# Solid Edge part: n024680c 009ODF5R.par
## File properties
Title: Bearing NA 4907
Comments: Sharon Richards Bearing Int. 011345 8160  R126-00  OD 55 ID 35 LENGTH 20
Template: Normal.par
Last saved by: Dan
Revision: 27
Application: Solid Edge
Document Number: P52-006
Project Name: Piston Pump P52
Mscpartversion: 2
ProtocolId (internal): P00040723104706972
Protocol (internal): P00040723104706972<@PID>[CalcData]<@EL>CalcResult=False<@EL>[LOGS]<@EL>7=2004/07/23 12:49:45 PM: ~The Strength Check is OK.~-2147483640~~~txtcheck<@EL>6=~--------------------------------------------------------------------------------------------~-2147483640~~~<@EL>5=2004/07/23 12:47:48 PM: ~The Strength Check is False.~255~~~txtcheck<@EL>4=2004/07/23 12:47:48 PM: ~Calculated bearing life is smaller then required.~255~~~var21<@EL>3=~--------------------------------------------------------------------------------------------~-2147483640~~~<@EL>2=2004/07/23 12:47:16 PM: ~The Strength Check is OK.~-2147483640~~~txtcheck<@EL>1=~--------------------------------------------------------------------------------------------~-2147483640~~~<@EL>8=~--------------------------------------------------------------------------------------------~-2147483640~~~<@EL>9=2004/07/23 12:50:31 PM: ~Bearing load is less than recommended minimum load.~255~~~var20<@EL>10=2004/07/23 12:50:31 PM: ~The Strength Check is False.~255~~~txtcheck<@EL>11=~--------------------------------------------------------------------------------------------~-2147483640~~~<@EL>12=2004/07/23 12:50:43 PM: ~Bearing load is less than recommended minimum load.~255~~~var20<@EL>13=2004/07/23 12:50:43 PM: ~The Strength Check is False.~255~~~txtcheck<@EL>[Data]<@EL>Scn1=1{ND<@EL>ot=1450{rpm<@EL>Lh_in=10000{h<@EL>V=1{ND<@EL>SIunits=1{ND<@EL>fd=1{ND<@EL>ft=100{°C<@EL>a1=90{%<@EL>d=35{mm<@EL>DD=55{mm<@EL>B=20{mm<@EL>r=0.6{mm<@EL>damin=39{mm<@EL>Damax=51{mm<@EL>ramax=0.6{mm<@EL>mass=0.17{kg<@EL>P=200{N<@EL>P0=200{N<@EL>s0=270{ND<@EL>Pz=1.33{W<@EL>Fmin=638{N<@EL>Lh=252938907.1{h<@EL>kn=6.55{ND<@EL>typ=NA 4907{<@EL>Ni=1{ND<@EL>Fr0=200{N<@EL>Fa0=0{N<@EL>n0=1450{rpm<@EL>t0=100{%<@EL>Ready=8{ND<@EL>Fw=42{mm<@EL>[Synchronize]<@EL>ChangedVars=<@EL>[Calc]<@EL>CalcName=BEARINGS<@EL>Optim=1<@EL>WizardMode=2<@EL>ScnVisible=1<@EL>Bmax=<@EL>Bmin=<@EL>Dmax=<@EL>Dmin=<@EL>DDmax=<@EL>DDmin=<@EL>[BaseView]<@EL>NewProt=P00040723104706972<@EL>OnT
BOM1: Bearing
BOM2: SKF NA 4907
Density: 0.0000078 kg/mm^3
Accuracy: 0.01
Material: steel
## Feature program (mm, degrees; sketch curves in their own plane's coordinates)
sketch for "unnamed RevolvedProtrusion 1" plane through (0, 0, 0) normal (0, 0, 1) x-axis (1, 0, 0)
  line (10, 22.955) -> (10, 27.5)
  line (10, 27.5) -> (-10, 27.5)
  line (-10, 27.5) -> (-10, 22.955)
  line (-10, 22.955) -> (-7, 22.955)
  line (-7, 23.61) -> (-7, 22.955)
  line (-7, 23.61) -> (7, 23.61)
  line (7, 23.61) -> (7, 22.955)
  line (10, 22.955) -> (7, 22.955)
revolve "unnamed RevolvedProtrusion 1" add
sketch for "unnamed RevolvedProtrusion 2" plane through (0, 0, 0) normal (0, 0, 1) x-axis (1, 0, 0)
  line (10, 20.1962) -> (7, 21)
  line (-7, 21) -> (7, 21)
  line (-7, 21) -> (-10, 20.1962)
  line (-10, 20.1962) -> (-10, 17.5)
  line (-10, 17.5) -> (10, 17.5)
  line (10, 17.5) -> (10, 20.1962)
revolve "unnamed RevolvedProtrusion 2" add
fillet "unnamed Round 1"
sketch for "unnamed RevolvedProtrusion 3" plane through (0, 0, 0) normal (0, 0, 1) x-axis (1, 0, 0)
  line (-7, 22.305) -> (7, 22.305)
  line (7, 23.605) -> (7, 22.305)
  line (-7, 23.605) -> (7, 23.605)
  line (-7, 22.305) -> (-7, 23.605)
revolve "unnamed RevolvedProtrusion 3" add about sketch line (-3.0987, 22.305) -> (3.798, 22.305)
pattern "unnamed Pattern 1" of "unnamed RevolvedProtrusion 3"
revolve "unnamed RevolvedProtrusion 4" add
revolve "unnamed RevolvedProtrusion 5" add
revolve "unnamed RevolvedProtrusion 6" add
revolve "unnamed RevolvedProtrusion 7" add
revolve "unnamed RevolvedProtrusion 8" add
revolve "unnamed RevolvedProtrusion 9" add
revolve "unnamed RevolvedProtrusion 10" add
revolve "unnamed RevolvedProtrusion 11" add
revolve "unnamed RevolvedProtrusion 12" add
revolve "unnamed RevolvedProtrusion 13" add
revolve "unnamed RevolvedProtrusion 14" add
revolve "unnamed RevolvedProtrusion 15" add
revolve "unnamed RevolvedProtrusion 16" add
revolve "unnamed RevolvedProtrusion 17" add
revolve "unnamed RevolvedProtrusion 18" add
revolve "unnamed RevolvedProtrusion 19" add
revolve "unnamed RevolvedProtrusion 20" add
revolve "unnamed RevolvedProtrusion 21" add
revolve "unnamed RevolvedProtrusion 22" add
revolve "unnamed RevolvedProtrusion 23" add
revolve "unnamed RevolvedProtrusion 24" add
revolve "unnamed RevolvedProtrusion 25" add
revolve "unnamed RevolvedProtrusion 26" add
revolve "unnamed RevolvedProtrusion 27" add
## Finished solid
Body 1: solid body, 93 faces, 216 edges, 100 vertices, 2 separate solids.
  Faces by surface: plane 56, cylinder 31, torus 4, cone 2
  Edges by curve: circle 216
Bounding box of the edges (mm; curved faces can reach further): 20.000 x 55.000 x 55.000, from (-10, -27.5, -27.5) to (10, 27.5, 27.5).
Cylindrical faces by radius (mm): R1.3 x25, R17.5 x1, R21 x1, R22.955 x2, R23.61 x1, R27.5 x1
Conical faces (half-angle, radius in mm at the cone's reference point): 15 deg R20.1962 x1, 15 deg R21 x1
Toroidal faces (ring radius, tube radius in mm): R18.1 r0.6 x2, R26.9 r0.6 x2
Planar faces by outward normal: +x 28, -x 28
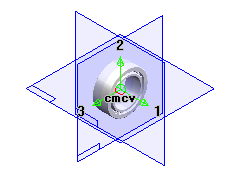
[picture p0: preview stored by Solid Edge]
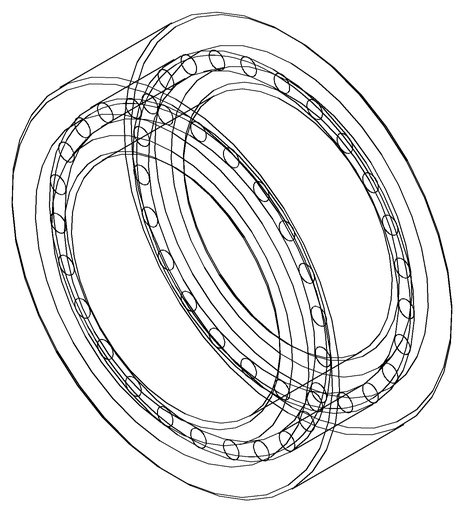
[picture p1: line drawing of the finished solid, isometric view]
